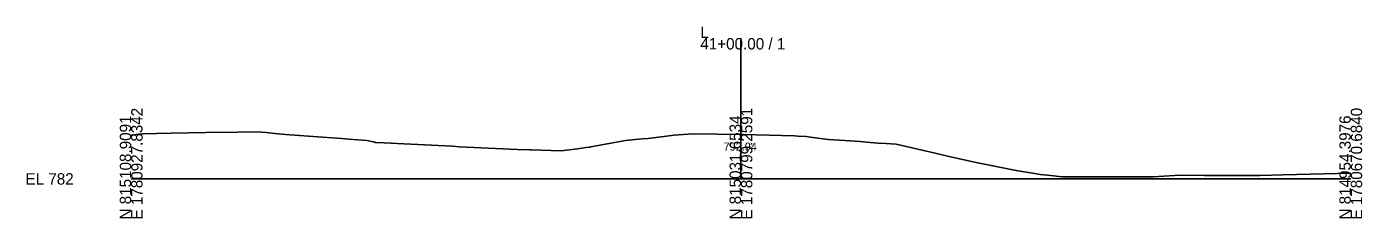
# Model space of a CAD drawing. Extents: x -26 to 7903, y -10 to 9573.
# Drawn here: x 974.3 to 1302.8, y 1990.3 to 2037.4 of the extents above; entities that cross this region are included whole.
import ezdxf

# ---------------------------------------------------------------- set-up
doc = ezdxf.new("R2010")
doc.units = 0
for name, color, linetype in [('Exist Cross Section Cell', 7, 'Continuous'), ('Exist XS Center Line Elevation Label', 7, 'Continuous'), ('Exist XS Ground Line', 7, 'Continuous')]:
    doc.layers.add(name, color=color, linetype=linetype)

msp = doc.modelspace()

# ---------------------------------------------------------------- linework, layer by layer
at = {"layer": 'Exist Cross Section Cell'}
for p, q in [((1150, 2000), (1150, 2034.65)), ((1000, 2000), (1150, 2000)), ((1150, 2000), (1300, 2000))]:
    msp.add_line(p, q, dxfattribs=at)
at = {"layer": 'Exist XS Ground Line'}
for p, q in [((1000, 2010.78), (1001.82, 2010.99)), ((1001.82, 2010.99), (1002.95, 2011.05)), ((1002.95, 2011.05), (1006.27, 2011.19)), ((1006.27, 2011.19), (1009.83, 2011.27)), ((1009.83, 2011.27), (1018.34, 2011.44)), ((1018.34, 2011.44), (1026.18, 2011.52)), ((1026.18, 2011.52), (1029.57, 2011.55)), ((1029.57, 2011.55), (1032.08, 2011.47)), ((1032.08, 2011.47), (1033.19, 2011.44)), ((1033.19, 2011.44), (1035.35, 2011.16)), ((1035.35, 2011.16), (1037.95, 2010.93)), ((1037.95, 2010.93), (1047.06, 2010.23)), ((1127.16, 2009.96), (1133.6, 2010.74)), ((1133.6, 2010.74), (1134.63, 2010.87)), ((1134.63, 2010.87), (1137.05, 2011.01)), ((1137.05, 2011.01), (1138.2, 2011.08)), ((1138.2, 2011.08), (1150, 2010.94)), ((1150, 2010.94), (1150.59, 2010.93)), ((1150.59, 2010.93), (1163.19, 2010.61)), ((1047.06, 2010.23), (1051.75, 2009.94)), ((1051.75, 2009.94), (1053.58, 2009.78)), ((1053.58, 2009.78), (1058, 2009.46)), ((1058, 2009.46), (1059.6, 2009.09)), ((1059.6, 2009.09), (1060.1, 2008.96)), ((1060.1, 2008.96), (1062.21, 2008.87)), ((1062.21, 2008.87), (1067.1, 2008.61)), ((1067.1, 2008.61), (1079.03, 2008.02)), ((1079.03, 2008.02), (1080.66, 2007.93)), ((1080.66, 2007.93), (1095.07, 2007.25)), ((1105.76, 2006.89), (1109.8, 2007.38)), ((1109.8, 2007.38), (1111.89, 2007.73)), ((1111.89, 2007.73), (1112.79, 2007.82)), ((1112.79, 2007.82), (1113.1, 2007.89)), ((1113.1, 2007.89), (1113.97, 2008.06)), ((1113.97, 2008.06), (1121.63, 2009.45)), ((1121.63, 2009.45), (1125.58, 2009.82)), ((1125.58, 2009.82), (1127.16, 2009.96)), ((1163.19, 2010.61), (1164, 2010.55)), ((1164, 2010.55), (1166.03, 2010.42)), ((1166.03, 2010.42), (1167.05, 2010.29)), ((1167.05, 2010.29), (1171.52, 2009.71)), ((1171.52, 2009.71), (1175.57, 2009.47)), ((1175.57, 2009.47), (1179.35, 2009.24)), ((1179.35, 2009.24), (1181.81, 2008.99)), ((1181.81, 2008.99), (1183.77, 2008.81)), ((1183.77, 2008.81), (1185.76, 2008.67)), ((1185.76, 2008.67), (1188.22, 2008.55)), ((1188.22, 2008.55), (1197.81, 2006.3)), ((1095.07, 2007.25), (1098.13, 2007.18)), ((1098.13, 2007.18), (1098.45, 2007.17)), ((1098.45, 2007.17), (1105.76, 2006.89)), ((1197.81, 2006.3), (1200.45, 2005.64)), ((1200.45, 2005.64), (1207.45, 2004.12)), ((1207.45, 2004.12), (1217.7, 2002.08)), ((1217.7, 2002.08), (1221.72, 2001.45)), ((1221.72, 2001.45), (1223.63, 2001.07)), ((1223.63, 2001.07), (1225.38, 2000.91)), ((1225.38, 2000.91), (1229.01, 2000.51)), ((1251.36, 2000.51), (1257.94, 2000.88)), ((1257.94, 2000.88), (1264.04, 2000.81)), ((1264.04, 2000.81), (1277.68, 2000.86)), ((1277.68, 2000.86), (1283.32, 2001)), ((1283.32, 2001), (1300, 2001.43)), ((1229.01, 2000.51), (1241.09, 2000.52)), ((1241.09, 2000.52), (1251.36, 2000.51))]:
    msp.add_line(p, q, dxfattribs=at)

# ---------------------------------------------------------------- texts
at = {"layer": 'Exist Cross Section Cell'}
for s, p in [('L', (1140, 2034.65)), ('41+00.00 / 1', (1140, 2031.85)), ('EL 782', (974, 1998.6))]:
    msp.add_text(s, height=2.8, dxfattribs=at).set_placement(p)
for s, p in [('E 1780927.8342', (1002.8, 1990)), ('E 1780799.2591', (1152.8, 1990)), ('E 1780670.6840', (1302.8, 1990)), ('N 815108.9091', (1000, 1990)), ('N 815031.6534', (1150, 1990)), ('N 814954.3976', (1300, 1990))]:
    msp.add_text(s, height=2.8, rotation=90, dxfattribs=at).set_placement(p)
at = {"layer": 'Exist XS Center Line Elevation Label'}
msp.add_text('792.94', height=2, dxfattribs=at).set_placement((1145.72, 2006.94))

doc.saveas('drawing.dxf')
